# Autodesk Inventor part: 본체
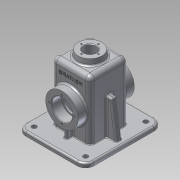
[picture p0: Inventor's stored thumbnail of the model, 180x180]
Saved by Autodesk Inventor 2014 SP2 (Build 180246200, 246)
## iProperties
Created: 2016-08
Part Number: 본체
Material: 알루미늄 6061
Document SubType Name: Modeling
Designer: user
Density: 2.71 g/cm^3
Appearance: 알루미늄 - 평지
Author: user
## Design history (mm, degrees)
sketch "스케치1"
  geometry: L1 (-57.5, 65)-(57.5, 65); L2 (57.5, 65)-(57.5, -65); L3 (57.5, -65)-(-57.5, -65); L4 (-57.5, -65)-(-57.5, 65); L5 (-57.5, 65)-(57.5, -65); L6 (57.5, 65)-(-57.5, -65); 1 further point
  constraints: 12 end point, 2 midpoint, 2 parallel, 1 horizontal, 1 perpendicular
  dimensions: "d0" = 115 distance of L2.end L3.end; "d1" = 130 distance of L1.end L2.end
extrude "돌출1" new body sketch "스케치1" distance "d2" = 10; taper "d3" = 0 deg
sketch "스케치2"
  geometry: L1 (-32.5, 32.5)-(32.5, 32.5); L2 (32.5, 32.5)-(32.5, -32.5); L3 (32.5, -32.5)-(-32.5, -32.5); L4 (-32.5, -32.5)-(-32.5, 32.5); L5 (-32.5, 32.5)-(32.5, -32.5); L6 (32.5, 32.5)-(-32.5, -32.5); 1 further point
  constraints: 12 end point, 2 midpoint, 2 parallel, 1 horizontal, 1 perpendicular
  dimensions: "d4" = 65 distance of L2.end L3.end; "d5" = 65 distance of L1.end L2.end
extrude "돌출2" join sketch "스케치2" distance "d6" = 100; taper "d7" = 0 deg
sketch "스케치3"
  geometry: L1 (90, -10)-(-25, -10) reference; C1 r 27.5 at (32.5, 45); 2 further points
  constraints: 1 centre point, 1 midpoint, 1 vertical alignment
  dimensions: "d8" = 55 diameter of C1; "d9" = 55 distance from line of L1 C1.centre
extrude "돌출3" join sketch "스케치3" distance "d10" = 15; taper "d11" = 0 deg
sketch "스케치4"
  geometry: L1 (-25, 10)-(90, 10) reference; C1 r 27.5 at (32.5, -45); 2 further points
  constraints: 1 centre point, 1 midpoint, 1 vertical alignment
  dimensions: "d12" = 55 diameter of C1; "d13" = 55 distance from line of L1 C1.centre
extrude "돌출4" join sketch "스케치4" distance "d14" = 15; taper "d15" = 0 deg
sketch "스케치7"
  geometry: C1 r 27.5 at (0, 0) reference; C2 r 17.5 at (0, 0); 1 further point
  constraints: 1 centre point, 1 coincident
  dimensions: "d23" = 35 diameter of C2
extrude "돌출7" cut sketch "스케치7" distance "d24" = 17; taper "d25" = 0 deg
sketch "스케치8"
  geometry: C1 r 17.5 at (0, 0) reference; C2 r 17.5 at (0, 0); 1 further point
  constraints: 1 centre point, 1 coincident
  dimensions: "d26" = 35 diameter of C2
extrude "돌출8" cut sketch "스케치8" distance "d27" = 17; taper "d28" = 0 deg
sketch "스케치9"
  geometry: C1 r 17.5 at (0, 0) reference; C2 r 15 at (0, 0); 1 further point
  constraints: 1 centre point, 1 coincident
  dimensions: "d29" = 30 diameter of C2
extrude "돌출9" cut sketch "스케치9" stored distance "d30" = 17; taper "d31" = 0 deg
sketch "스케치11" dims "d35" = 42
  geometry: C1 r 17.5 at (0, 0) reference; C2 r 27.5 at (0, 0) reference; 6 further points
  constraints: 2 vertical alignment, 1 coincident, 7 other
  dimensions: "d38" = 360 deg dimension on C1.centre point (0, 21) (derived)
hole "구멍1" sketch "스케치11" at (0, 21), (-21, 0), (0, -21), (21, 0) diameter "d40" = 3.242; stored, may be unused: countersink angle "d44" = 90 deg, drill point angle "d46" = 118 deg; dims "d41" = 8, "d42" = 4, "d43" = 2, "d45" = 10
sketch "스케치12" dims "d47" = 42
  geometry: C1 r 17.5 at (0, 0) reference; C2 r 27.5 at (0, 0) reference; 6 further points
  constraints: 2 vertical alignment, 1 coincident, 7 other
  dimensions: "d50" = 360 deg dimension on C1.centre point (0, -21) (derived)
hole "구멍2" sketch "스케치12" at (0, -21), (21, 0), (0, 21), (-21, 0) diameter "d52" = 3.242; stored, may be unused: countersink angle "d56" = 90 deg, drill point angle "d58" = 118 deg; dims "d53" = 8, "d54" = 4, "d55" = 2, "d57" = 10
sketch "스케치14"
  geometry: L1 (-32.5, 10)-(-32.5, 110) reference; L2 (32.5, 10)-(32.5, 110) reference; L3 (-57.5, 10)-(57.5, 10) reference; L4 (-32.5, 70)-(-41.068, 70); L5 (-41.068, 70)-(-49.5, 10); L6 (-57.5, 0)-(-57.5, 10) reference; 1 further point
  constraints: 4 end point, 2 point on line, 1 parallel
  dimensions: "d71" = 8 distance of L5.end L3.start; "d72" = 8 deg angle of L5 L6; "d73" = 70 distance from line of L4 L6.start
feature "리브1" sketch "스케치14" dims "d74" = 1, "d75" = 10, "d76" = 0, "d77" = 0, "d78" = 1, "d79" = 1
sketch "스케치15"
  geometry: L1 (-32.5, 27.5)-(-47.5, 27.5) reference; L2 (-32.5, 10)-(-32.5, 110) reference; L3 (65, 10)-(-65, 10) reference; L4 (-42.5, 27.5)-(-42.5, 10); 1 further point
  constraints: 2 end point, 2 point on line, 1 perpendicular
feature "리브2" sketch "스케치15" dims "d81" = 1, "d82" = 6, "d83" = 0, "d84" = 0, "d85" = 1, "d86" = 1
sketch "스케치16"
  geometry: L1 (52.5, -60)-(-52.5, -60); L2 (-52.5, -60)-(-52.5, 60); L3 (-52.5, 60)-(52.5, 60); L4 (52.5, 60)-(52.5, -60); L5 (52.5, -60)-(-52.5, 60); L6 (-52.5, -60)-(52.5, 60); L7 (-57.5, -65)-(57.5, -65) reference; L8 (57.5, -65)-(57.5, 65) reference; L9 (57.5, 65)-(-57.5, 65) reference; L10 (-57.5, 65)-(-57.5, -65) reference; 1 further point
  constraints: 12 end point, 2 midpoint, 2 parallel, 1 horizontal, 1 perpendicular
  dimensions: "d87" = 105 distance of L2.end L3.end; "d88" = 120 distance of L1.end L2.end
extrude "돌출11" cut sketch "스케치16" distance "d89" = 3; taper "d90" = 0 deg
chamfer "모따기1" distance "d91" = 1; stored, may be unused: second distance "d92" = 2, angle "d93" = 45 deg
chamfer "모따기2" distance "d94" = 1; stored, may be unused: second distance "d95" = 2, angle "d96" = 45 deg
fillet "모깎기1" dims "d100" = 14
fillet "모깎기2" dims "d101" = 3
hole "구멍4" diameter "d104" = 8; stored, may be unused: countersink angle "d108" = 90 deg, drill point angle "d110" = 118 deg; dims "d105" = 7, "d106" = 4, "d107" = 2, "d109" = 9, "d111" = 10, "d112" = 10
hole "구멍5" diameter "d115" = 8; stored, may be unused: countersink angle "d119" = 90 deg, drill point angle "d121" = 118 deg; dims "d113" = 10, "d114" = 10, "d116" = 7, "d117" = 4, "d118" = 2, "d120" = 9
hole "구멍6" diameter "d124" = 8; stored, may be unused: countersink angle "d128" = 90 deg, drill point angle "d130" = 118 deg; dims "d122" = 10, "d123" = 10, "d125" = 7, "d126" = 4, "d127" = 2, "d129" = 9
hole "구멍7" diameter "d133" = 8; stored, may be unused: countersink angle "d137" = 90 deg, drill point angle "d139" = 118 deg; dims "d131" = 10, "d132" = 10, "d134" = 7, "d135" = 4, "d136" = 2, "d138" = 9
fillet "모깎기3" dims "d140" = 8
fillet "모깎기4" dims "d141" = 9
fillet "모깎기6" dims "d143" = 3
fillet "모깎기7" dims "d144" = 3
fillet "모깎기9" dims "d146" = 0.3
fillet "모깎기10" dims "d147" = 3
fillet "모깎기11" dims "d148" = 3
fillet "모깎기12" dims "d149" = 3
fillet "모깎기13" dims "d150" = 3
fillet "모깎기14" dims "d151" = 3
fillet "모깎기15" dims "d152" = 3
fillet "모깎기16" dims "d153" = 1
node "작업 평면1"
node "작업 평면2"
sketch "스케치18"
  geometry: C1 r 20 at (0, 0); 1 further point
  constraints: 1 centre point, 1 coincident
  dimensions: "d160" = 40 diameter of C1
extrude "돌출12" join sketch "스케치18" stored distance "d161" = 3; taper "d162" = 7 deg
sketch "스케치19"
  geometry: C1 r 10.5 at (0, 0); 1 further point
  constraints: 1 centre point, 1 coincident
  dimensions: "d163" = 21 diameter of C1
extrude "돌출13" cut sketch "스케치19" stored distance "d164" = 3; taper "d165" = 0 deg
sketch "스케치20" dims "d166" = 29
  geometry: 6 further points
  constraints: 2 vertical alignment, 1 coincident, 7 other
  dimensions: "d169" = 360 deg dimension on point (0, 0) point (0, 14.5) (derived)
hole "구멍8" sketch "스케치20" at (0, 14.5), (-14.5, 0), (0, -14.5), (14.5, 0) diameter "d171" = 2.459; stored, may be unused: countersink angle "d175" = 90 deg, drill point angle "d177" = 118 deg; dims "d172" = 7, "d173" = 4, "d174" = 2, "d176" = 9
fillet "모깎기17" dims "d178" = 3
chamfer "모따기4" distance "d179" = 1; stored, may be unused: second distance "d180" = 2, angle "d181" = 45 deg
sketch "스케치21"
  geometry: L1 (-27.5, 105)-(27.5, 105); L2 (27.5, 105)-(27.5, 0); L3 (27.5, 0)-(-27.5, 0); L4 (-27.5, 0)-(-27.5, 105); L5 (32.5, 102)-(32.5, 73.166) reference; L6 (-32.5, 73.166)-(-32.5, 102) reference; L7 (-24.5, 110)-(24.5, 110) reference; 2 further points
  constraints: 8 end point, 2 parallel, 1 coincident, 1 horizontal, 1 midpoint, 1 perpendicular
  dimensions: "d182" = 5 distance between parallel lines of L5 L2; "d183" = 5 distance between parallel lines of L7 L1
extrude "돌출14" cut sketch "스케치21" stored distance "d184" = 55; taper "d185" = 0 deg
sketch "스케치22"
  geometry: L1 (-20, 120)-(20, 120) reference; L2 (32.5, 11)-(32.5, 102) reference; L3 (-32.5, 102)-(-32.5, 11) reference; 2 further points
  constraints: 1 other
  dimensions: "d186" = 26 distance from line of point (0, 94) L1; "d187" = 32.5 distance from line of point (0, 94) L3
feature "엠보싱2" sketch "스케치22" dims "d188" = 0.5, "d189" = 0
node "솔리드1"
mirror "대칭1"
mirror "대칭2"
node "투영된 루프1"
node "투영된 루프2"
node "투영된 루프3"
node "투영된 루프4"
other parameters: "d154" = -42
